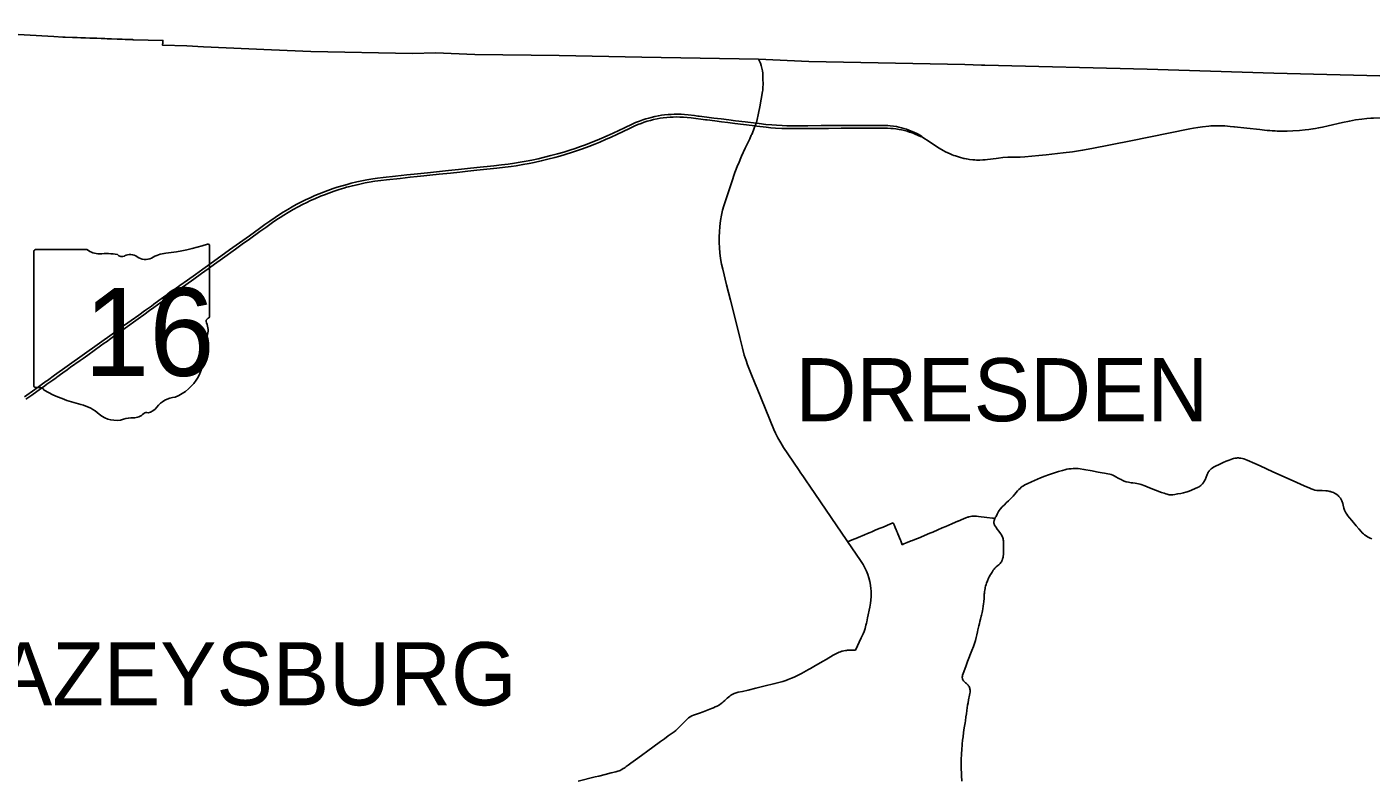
# Model space of a CAD drawing. Extents: x 1761803 to 2441803, y 509895 to 949895.
# Drawn here: x 2077957 to 2120541, y 859538 to 883403 of the extents above; entities that cross this region are included whole.
import ezdxf

# ---------------------------------------------------------------- set-up
doc = ezdxf.new("R2010")
doc.units = 0
for name, color, linetype in [('GM_X_County', 7, 'Continuous'), ('GM_X_County_Road', 7, 'Continuous'), ('GM_X_Minor_Lake', 7, 'Continuous'), ('GM_X_Township_Road', 7, 'Continuous')]:
    doc.layers.add(name, color=color, linetype=linetype)

msp = doc.modelspace()

# ---------------------------------------------------------------- linework, layer by layer
at = {"layer": 'GM_X_County'}
msp.add_lwpolyline([(2073355, 883403), (2078806, 883101), (2079100, 883079), (2079172, 883079), (2079403, 883070), (2079554, 883063), (2079668, 883059), (2079750, 883056), (2079816, 883053), (2079947, 883049), (2080078, 883046), (2080176, 883044), (2080307, 883039), (2080422, 883033), (2080504, 883028), (2080639, 883022), (2080813, 883013), (2080878, 883011), (2080976, 883009), (2081074, 883006), (2081255, 883000), (2081305, 882998), (2081323, 882996), (2081333, 882993), (2081338, 882991), (2082266, 882974), (2082260, 882880), (2082255, 882851), (2082249, 882829), (2083019, 882800), (2083552, 882776), (2085709, 882680), (2086949, 882622), (2090175, 882557), (2090899, 882579), (2092146, 882528), (2094817, 882501), (2097434, 882447), (2101139, 882380), (2102727, 882302), (2107674, 882210), (2108199, 882192), (2108299, 882191), (2113442, 882063), (2117464, 881939), (2121664, 881828)], dxfattribs=at)
at = {"layer": 'GM_X_Minor_Lake'}
for points in [[(2101275, 881509), (2101277, 881555), (2101276, 881785), (2101273, 881844), (2101268, 881937), (2101259, 882015), (2101243, 882096), (2101222, 882175), (2101194, 882253), (2101139, 882380)], [(2101135, 880666), (2101174, 880874), (2101260, 881359), (2101266, 881400), (2101269, 881430), (2101272, 881457), (2101274, 881494), (2101275, 881509)], [(2077877, 871679), (2078210, 871918), (2078570, 872176), (2078608, 872203), (2078836, 872367), (2080660, 873672), (2080913, 873853), (2081260, 874101), (2081500, 874273), (2081687, 874406), (2081900, 874559), (2081977, 874614), (2082141, 874732), (2082286, 874837), (2082566, 875036), (2082806, 875208), (2083047, 875379), (2083300, 875561), (2083526, 875723), (2083753, 875887), (2084379, 876335), (2085005, 876785), (2085325, 877014), (2085498, 877138), (2085658, 877252), (2085820, 877364), (2085956, 877455), (2086081, 877535), (2086221, 877619), (2086363, 877701), (2086492, 877772), (2086637, 877848), (2086784, 877920), (2086933, 877990), (2087082, 878056), (2087218, 878113), (2087355, 878168), (2087494, 878219), (2087664, 878279), (2087788, 878320), (2087992, 878381), (2088028, 878391), (2088134, 878422), (2088229, 878447), (2088405, 878489), (2088565, 878524), (2088726, 878555), (2088919, 878589), (2089065, 878611), (2089244, 878633), (2089635, 878677), (2089994, 878714), (2090222, 878737), (2090434, 878759), (2090647, 878781), (2091315, 878852), (2091625, 878884), (2091918, 878915), (2092212, 878947), (2092750, 879002), (2092995, 879029), (2093207, 879056), (2093401, 879084), (2093580, 879112), (2093773, 879147), (2093950, 879182), (2094159, 879226), (2094351, 879271), (2094557, 879323), (2094763, 879379), (2094968, 879438), (2095156, 879496), (2095328, 879552), (2095499, 879610), (2095653, 879667), (2095836, 879738), (2096019, 879810), (2096171, 879873), (2096336, 879946), (2096529, 880036), (2096884, 880206), (2097136, 880325), (2097241, 880371), (2097363, 880419), (2097471, 880458), (2097564, 880489), (2097658, 880516), (2097738, 880536), (2097849, 880563), (2097961, 880586), (2098058, 880602), (2098156, 880614), (2098270, 880626), (2098368, 880632), (2098466, 880636), (2098564, 880636), (2098679, 880633), (2098793, 880626), (2098907, 880615), (2099102, 880592), (2099216, 880578), (2099256, 880574), (2099493, 880545), (2099720, 880516), (2099948, 880487), (2100192, 880457), (2100404, 880430), (2100713, 880393), (2101057, 880350), (2101153, 880338), (2101364, 880314), (2101560, 880295), (2101708, 880284), (2101888, 880275), (2102036, 880270), (2102200, 880269), (2102462, 880269), (2102692, 880271), (2103118, 880274), (2103265, 880275), (2103364, 880275), (2103708, 880278), (2104053, 880281), (2104299, 880282), (2104950, 880282), (2105031, 880283), (2105146, 880281), (2105227, 880277), (2105309, 880270), (2105406, 880259), (2105503, 880243), (2105583, 880227), (2105663, 880208), (2105741, 880186), (2105819, 880161), (2105896, 880134), (2106002, 880091), (2106077, 880058), (2106131, 880031), (2106197, 879999), (2106263, 879963), (2106285, 879946), (2106310, 879921)], [(2101012, 880221), (2101029, 880266), (2101057, 880350), (2101066, 880377), (2101093, 880472), (2101126, 880616), (2101135, 880666)], [(2077928, 871603), (2078114, 871736), (2078274, 871851), (2078528, 872032), (2078594, 872080), (2078781, 872214), (2078884, 872288), (2078901, 872300), (2079101, 872444), (2079234, 872540), (2079340, 872617), (2079648, 872835), (2079741, 872901), (2079888, 873007), (2080287, 873294), (2080407, 873380), (2080474, 873427), (2080621, 873533), (2080655, 873557), (2081486, 874155), (2081659, 874280), (2081846, 874413), (2081977, 874508), (2082098, 874595), (2082605, 874957), (2082792, 875090), (2082892, 875161), (2082993, 875232), (2083246, 875414), (2083485, 875588), (2083698, 875740), (2083898, 875884), (2084151, 876066), (2084565, 876361), (2084777, 876515), (2085005, 876676), (2085337, 876915), (2085524, 877049), (2085738, 877202), (2085872, 877296), (2085981, 877369), (2086092, 877439), (2086232, 877524), (2086388, 877614), (2086546, 877701), (2086692, 877778), (2086824, 877844), (2086942, 877900), (2087078, 877959), (2087259, 878035), (2087381, 878084), (2087519, 878136), (2087690, 878196), (2087845, 878247), (2088002, 878296), (2088087, 878321), (2088144, 878337), (2088271, 878370), (2088415, 878403), (2088672, 878457), (2088801, 878482), (2088979, 878511), (2089174, 878538), (2089353, 878560), (2089777, 878604), (2090103, 878638), (2090316, 878660), (2090528, 878681), (2090723, 878701), (2091017, 878732), (2091375, 878772), (2091669, 878802), (2091930, 878830), (2092207, 878860), (2092843, 878926), (2093104, 878955), (2093299, 878981), (2093461, 879005), (2093671, 879040), (2093865, 879075), (2094025, 879107), (2094249, 879158), (2094456, 879207), (2094678, 879265), (2094836, 879308), (2095009, 879360), (2095244, 879433), (2095368, 879474), (2095554, 879540), (2095754, 879614), (2095952, 879691), (2096104, 879753), (2096285, 879831), (2096465, 879910), (2096643, 879993), (2097042, 880185), (2097191, 880253), (2097312, 880305), (2097418, 880347), (2097511, 880381), (2097605, 880411), (2097716, 880442), (2097811, 880465), (2097924, 880489), (2098021, 880506), (2098118, 880520), (2098232, 880533), (2098331, 880542), (2098429, 880547), (2098527, 880548), (2098642, 880547), (2098757, 880542), (2098872, 880533), (2099002, 880519), (2099452, 880463), (2099507, 880456), (2099751, 880426), (2099962, 880400), (2100158, 880374), (2100385, 880345), (2100929, 880278)], [(2100333, 878630), (2100389, 878794), (2100482, 879031), (2100497, 879068), (2100599, 879310), (2100713, 879565), (2100855, 879860), (2100906, 879970), (2100918, 879994), (2100976, 880130), (2101012, 880221)], [(2100929, 880278), (2101029, 880266), (2101085, 880259), (2101378, 880224), (2101525, 880209), (2101672, 880198), (2101868, 880187), (2102015, 880182), (2102179, 880180), (2102442, 880182), (2102704, 880185), (2103294, 880186), (2103353, 880187), (2103753, 880189), (2104311, 880193), (2104725, 880192)], [(2110245, 879351), (2110784, 879408), (2111077, 879445), (2111402, 879496), (2111692, 879550), (2112931, 879796), (2113494, 879909), (2114797, 880171), (2114915, 880194), (2115055, 880218), (2115201, 880239), (2115397, 880259), (2115468, 880264), (2115587, 880268), (2115650, 880269), (2115774, 880267), (2115905, 880263), (2116075, 880250)], [(2116075, 880250), (2116191, 880240), (2116215, 880239), (2116606, 880195), (2117014, 880148), (2117159, 880133), (2117244, 880124), (2117332, 880118), (2117409, 880112), (2117445, 880109)], [(2117445, 880109), (2117498, 880105), (2117564, 880102), (2117701, 880099), (2117881, 880101), (2118062, 880107), (2118275, 880120), (2118455, 880138), (2118565, 880153), (2118699, 880172), (2118783, 880187), (2118874, 880204), (2119000, 880230), (2119181, 880270), (2119629, 880372), (2119854, 880420), (2120047, 880455), (2120242, 880481), (2120405, 880497), (2120534, 880506), (2120612, 880511), (2120944, 880526)], [(2104725, 880192), (2104894, 880191), (2105109, 880192), (2105224, 880190), (2105323, 880185), (2105405, 880179), (2105487, 880169), (2105585, 880154), (2105666, 880138), (2105762, 880116), (2105842, 880095), (2105920, 880070), (2105998, 880042), (2106055, 880020), (2106216, 879949), (2106261, 879931), (2106280, 879925), (2106310, 879921)], [(2106310, 879921), (2106569, 879753), (2106774, 879616), (2106857, 879563), (2106984, 879488), (2107056, 879448), (2107130, 879412), (2107205, 879378), (2107266, 879354), (2107327, 879330), (2107372, 879314), (2107435, 879294), (2107500, 879273), (2107638, 879234), (2107657, 879230), (2107722, 879218), (2107774, 879210)], [(2108666, 879237), (2108741, 879247), (2108871, 879261), (2109035, 879270), (2109428, 879278), (2109576, 879286), (2110017, 879327), (2110245, 879351)], [(2107774, 879210), (2107821, 879203), (2107920, 879192), (2107986, 879186), (2108036, 879184), (2108149, 879184), (2108241, 879187), (2108310, 879192), (2108383, 879199), (2108666, 879237)], [(2102529, 869187), (2102456, 869295), (2102419, 869348), (2102059, 869877), (2101923, 870082), (2101838, 870222), (2101750, 870380), (2101676, 870526), (2101623, 870645), (2101090, 871951), (2101032, 872091), (2100891, 872437), (2100787, 872696), (2100738, 872835), (2100684, 873007), (2100623, 873228), (2100540, 873562), (2100370, 874247), (2100247, 874741), (2100122, 875233), (2099999, 875727), (2099964, 875887), (2099933, 876064), (2099909, 876243), (2099895, 876406), (2099888, 876570), (2099888, 876750), (2099894, 876914), (2099899, 876973), (2099904, 877019), (2099909, 877077), (2099934, 877272), (2099962, 877434), (2099998, 877593), (2100037, 877735), (2100118, 877985), (2100331, 878623), (2100333, 878630)], [(2108618, 867824), (2108645, 867870), (2108658, 867895), (2108691, 867966), (2108721, 868024), (2108738, 868053), (2108756, 868081), (2108787, 868119), (2108854, 868192), (2108922, 868263), (2108979, 868322), (2109050, 868390), (2109144, 868481), (2109201, 868539), (2109256, 868600), (2109342, 868699), (2109386, 868748), (2109421, 868782), (2109458, 868815), (2109484, 868836), (2109525, 868864), (2109568, 868889), (2109640, 868924), (2109783, 868989), (2110070, 869118), (2110204, 869171), (2110318, 869210), (2110417, 869243), (2110634, 869313), (2110759, 869352), (2110839, 869373), (2110903, 869387), (2110968, 869398), (2111034, 869406), (2111099, 869411), (2111149, 869412), (2111214, 869411), (2111264, 869407), (2111329, 869400), (2111443, 869381), (2111701, 869333), (2111845, 869306), (2111891, 869298), (2112018, 869276), (2112099, 869262), (2112196, 869246), (2112261, 869233), (2112309, 869220), (2112355, 869202), (2112400, 869181), (2112458, 869151), (2112530, 869110), (2112572, 869085), (2112619, 869059), (2112658, 869038), (2112692, 869023), (2112722, 869010), (2112750, 869000), (2112778, 868992), (2112859, 868975), (2112939, 868961), (2112987, 868955), (2113069, 868947), (2113118, 868940), (2113167, 868930), (2113214, 868918), (2113261, 868902), (2113369, 868862), (2113522, 868802), (2113904, 868656), (2113980, 868627), (2114038, 868606), (2114084, 868593), (2114144, 868580), (2114183, 868577), (2114219, 868577), (2114256, 868580), (2114324, 868590), (2114409, 868605), (2114510, 868623), (2114597, 868643), (2114667, 868660), (2114714, 868674), (2114776, 868696), (2114852, 868726), (2114972, 868778), (2115046, 868812), (2115089, 868835), (2115117, 868853), (2115143, 868872), (2115179, 868905), (2115201, 868928), (2115222, 868953), (2115241, 868979), (2115257, 869007), (2115279, 869051), (2115317, 869142), (2115348, 869218), (2115369, 869263), (2115383, 869292), (2115400, 869321), (2115410, 869334), (2115431, 869360), (2115454, 869384), (2115479, 869405), (2115506, 869425), (2115548, 869450), (2115607, 869481), (2115726, 869537), (2115859, 869599), (2115949, 869640), (2116039, 869679), (2116101, 869701), (2116148, 869716), (2116180, 869725), (2116228, 869736), (2116277, 869743), (2116310, 869745), (2116343, 869746), (2116376, 869744), (2116409, 869740), (2116464, 869730), (2116511, 869715), (2116560, 869696), (2116609, 869675), (2116687, 869641), (2116784, 869597), (2116927, 869535), (2117182, 869422), (2117271, 869381), (2117525, 869267), (2117885, 869106), (2118185, 868973), (2118424, 868865), (2118597, 868786), (2118644, 868765), (2118700, 868744), (2118758, 868729), (2118825, 868717), (2118890, 868713), (2118986, 868710), (2119105, 868704), (2119158, 868699), (2119205, 868692), (2119234, 868687), (2119267, 868678), (2119275, 868675), (2119305, 868665), (2119344, 868646), (2119386, 868626), (2119422, 868605), (2119462, 868579), (2119493, 868553), (2119521, 868524), (2119545, 868495), (2119567, 868467), (2119590, 868430), (2119613, 868391), (2119628, 868355), (2119638, 868331), (2119648, 868300), (2119660, 868252), (2119681, 868156), (2119689, 868125), (2119700, 868094), (2119719, 868050), (2119742, 868007), (2119768, 867965), (2119806, 867912), (2119857, 867848), (2119931, 867761), (2120071, 867600), (2120155, 867499), (2120229, 867413), (2120262, 867377), (2120298, 867343), (2120335, 867312), (2120387, 867273), (2120428, 867246), (2120470, 867221), (2120514, 867200), (2120559, 867181)], [(2103956, 867094), (2103933, 867130), (2103433, 867863), (2102758, 868852), (2102646, 869016), (2102533, 869181), (2102529, 869187)], [(2107446, 867739), (2107464, 867747), (2107629, 867819), (2107704, 867850), (2107750, 867865), (2107774, 867873), (2107797, 867879), (2107845, 867889), (2107893, 867896), (2107942, 867900), (2107991, 867901), (2108040, 867900), (2108105, 867895), (2108363, 867864)], [(2108363, 867864), (2108364, 867864), (2108545, 867843), (2108581, 867836), (2108618, 867824)], [(2103956, 867094), (2103995, 867106), (2104009, 867111), (2104026, 867118), (2104157, 867172), (2104215, 867196), (2104293, 867229), (2104490, 867311), (2104582, 867348), (2104672, 867386), (2104722, 867407), (2104771, 867428), (2104854, 867463), (2104984, 867516), (2105083, 867556), (2105318, 867654), (2105404, 867689)], [(2105404, 867689), (2105433, 867623), (2105464, 867547), (2105495, 867472), (2105508, 867442), (2105520, 867413), (2105539, 867369), (2105551, 867340), (2105631, 867146), (2105642, 867116), (2105653, 867086), (2105666, 867056), (2105689, 866997)], [(2105689, 866997), (2105740, 867021), (2105841, 867063), (2105975, 867118), (2106017, 867135), (2106140, 867183), (2106167, 867194), (2106200, 867208), (2106562, 867360), (2106652, 867399), (2106818, 867469), (2106953, 867527), (2107073, 867579), (2107254, 867656), (2107281, 867668), (2107446, 867739)], [(2107577, 859502), (2107573, 859547), (2107567, 859645), (2107563, 859760), (2107557, 859891), (2107556, 860021), (2107556, 860138), (2107559, 860236), (2107562, 860320), (2107567, 860401), (2107573, 860480), (2107578, 860550), (2107582, 860611), (2107588, 860674), (2107598, 860800), (2107613, 860907), (2107632, 861051), (2107652, 861190), (2107679, 861349), (2107690, 861412), (2107706, 861539), (2107721, 861634), (2107737, 861747), (2107759, 861910), (2107772, 861991), (2107787, 862079), (2107820, 862233), (2107832, 862280), (2107838, 862329), (2107839, 862361), (2107837, 862393), (2107832, 862425), (2107829, 862441), (2107818, 862471), (2107805, 862501), (2107789, 862530), (2107779, 862543), (2107758, 862567), (2107746, 862578), (2107722, 862601), (2107696, 862620), (2107658, 862652), (2107634, 862676), (2107624, 862688), (2107614, 862702), (2107606, 862717), (2107599, 862733), (2107594, 862749), (2107591, 862765), (2107589, 862782), (2107590, 862799), (2107594, 862832), (2107601, 862864), (2107616, 862912), (2107666, 863051), (2107711, 863174), (2107755, 863298), (2107796, 863405), (2107850, 863542), (2107893, 863649), (2107940, 863772), (2107974, 863862), (2108004, 863957), (2108032, 864058), (2108051, 864139), (2108070, 864235), (2108085, 864302), (2108095, 864342), (2108107, 864387), (2108116, 864424), (2108133, 864499), (2108147, 864562), (2108168, 864639), (2108191, 864732), (2108199, 864764), (2108218, 864848), (2108228, 864903), (2108238, 864966), (2108251, 865045), (2108263, 865127), (2108271, 865192), (2108280, 865304), (2108283, 865384), (2108287, 865433), (2108291, 865463), (2108293, 865478), (2108297, 865510), (2108304, 865558), (2108312, 865606), (2108318, 865638), (2108329, 865686), (2108342, 865734), (2108358, 865781), (2108388, 865857), (2108421, 865933), (2108442, 865977), (2108462, 866012), (2108466, 866020), (2108491, 866063), (2108535, 866132), (2108571, 866186), (2108600, 866226), (2108622, 866251), (2108644, 866275), (2108668, 866297), (2108718, 866339), (2108743, 866360), (2108767, 866383), (2108789, 866406), (2108809, 866431), (2108827, 866458), (2108843, 866486), (2108849, 866501), (2108856, 866516), (2108861, 866530), (2108866, 866545), (2108875, 866572), (2108882, 866602), (2108886, 866634), (2108891, 866683), (2108893, 866765), (2108894, 866863), (2108895, 866962), (2108893, 867059), (2108890, 867124), (2108886, 867156), (2108880, 867188), (2108872, 867219), (2108860, 867250), (2108846, 867279), (2108831, 867307), (2108804, 867348), (2108747, 867428), (2108698, 867493), (2108649, 867560), (2108630, 867587), (2108613, 867615), (2108606, 867630), (2108599, 867646), (2108595, 867662), (2108591, 867678), (2108590, 867695), (2108590, 867712), (2108592, 867729), (2108595, 867746), (2108600, 867762), (2108618, 867824)], [(2104697, 865595), (2104681, 865719), (2104658, 865833), (2104629, 865944), (2104593, 866054), (2104551, 866161), (2104501, 866265), (2104446, 866366), (2104367, 866492), (2103956, 867094)], [(2104209, 863651), (2104389, 864045), (2104447, 864175), (2104479, 864251), (2104511, 864344), (2104538, 864447), (2104553, 864506), (2104564, 864554), (2104592, 864680), (2104664, 865017), (2104685, 865147), (2104696, 865244), (2104703, 865359), (2104704, 865396), (2104704, 865429), (2104704, 865471), (2104703, 865502), (2104701, 865535), (2104697, 865594), (2104697, 865595)], [(2103156, 863295), (2103279, 863365), (2103499, 863496), (2103600, 863550), (2103690, 863591), (2103729, 863606), (2103774, 863621), (2103793, 863628), (2103839, 863639), (2103894, 863645), (2103932, 863649), (2103942, 863651), (2103990, 863654), (2104075, 863654), (2104209, 863651)], [(2102183, 862765), (2102212, 862777), (2102285, 862810), (2102331, 862831), (2102477, 862906), (2102500, 862918), (2102649, 863002), (2102721, 863041), (2102777, 863076), (2102890, 863142), (2103156, 863295)], [(2095419, 859507), (2095956, 859639), (2096072, 859668), (2096279, 859719), (2096470, 859766), (2096614, 859801), (2096681, 859822), (2096718, 859835), (2096750, 859848), (2096780, 859863), (2096809, 859880), (2096846, 859902), (2096879, 859922), (2096908, 859940), (2096946, 859968), (2097002, 860009), (2097092, 860073), (2097242, 860183), (2097426, 860318), (2097626, 860463), (2097784, 860580), (2098034, 860764), (2098153, 860851), (2098272, 860939), (2098337, 860988), (2098457, 861072), (2098510, 861112), (2098560, 861154), (2098644, 861233), (2098779, 861375), (2098859, 861457), (2098889, 861485), (2098921, 861509), (2098974, 861546), (2099017, 861570), (2099077, 861596), (2099169, 861630), (2099261, 861663), (2099385, 861707), (2099646, 861806), (2099707, 861830), (2099765, 861856), (2099826, 861886), (2099898, 861926), (2099952, 861963), (2099984, 861989), (2100019, 862017), (2100063, 862058), (2100146, 862139), (2100221, 862203), (2100260, 862231), (2100317, 862263), (2100362, 862282), (2100424, 862304), (2100487, 862321), (2100631, 862349), (2100808, 862386), (2101046, 862448), (2101300, 862511), (2101653, 862599), (2101903, 862667), (2101997, 862695), (2102075, 862722), (2102183, 862765)]]:
    msp.add_lwpolyline(points, dxfattribs=at)
at = {"layer": 'GM_X_Township_Road'}
for p, q in [((2083745, 874241), (2083745, 876452)), ((2078176, 876274), (2078176, 872048)), ((2079862, 876347), (2078231, 876347)), ((2083744, 874241), (2083745, 874241))]:
    msp.add_line(p, q, dxfattribs=at)
for centre, radius, start, end in [((2081761, 882109), 5905, 275.8445, 288.9065), ((2083683, 876461), 62, 351.8621, 97.738), ((2078240, 876283), 64.5, 98.1301, 188.1301), ((2080250, 876837), 626, 231.6195, 271.1119), ((2080457, 873974), 2246, 80.4867, 94.9883), ((2080967, 876305), 181, 219.7921, 297.1024), ((2081232, 875817), 375, 54.4667, 119.1411), ((2081717, 876487), 452, 233.8562, 294.8282), ((2082514, 875056), 1188, 97.3462, 120.7689), ((2083678, 874232), 66.3, 289.6038, 7.7341), ((2083730, 874078), 95.9, 107.944, 210.337), ((2083120, 873799), 576, 340.033, 23.6496), ((2083967, 873315), 419, 136.8065, 186.9296), ((2082092, 873034), 1477, 292.3089, 8.9858), ((2078240, 872038), 65.1, 171.9584, 258.3066), ((2078250, 872471), 497, 267.339, 280.6039), ((2078352, 871804), 179, 29.7484, 93.2717), ((2080613, 875601), 4265, 240.4129, 257.1985), ((2079342, 870149), 1334, 47.1842, 75.836), ((2081690, 871638), 477, 282.8732, 323.2771), ((2082715, 870861), 809, 94.4031, 142.5768), ((2080785, 871783), 847, 230.7004, 286.2918), ((2081274, 870321), 696, 85.6951, 111.2099), ((2081336, 871466), 451, 268.777, 315.5493), ((2081744, 871057), 127, 65.7517, 132.6484)]:
    msp.add_arc(centre, radius, start, end, dxfattribs=at)

# ---------------------------------------------------------------- texts
at = {"layer": 'GM_X_County_Road'}
for s, p in [('DRESDEN', (2102305, 870908)), ('FRAZEYSBURG', (2073413, 861908))]:
    msp.add_text(s, height=2000, rotation=0, dxfattribs=at).set_placement(p)
at = {"layer": 'GM_X_Township_Road'}
msp.add_text('16', height=2784.4, dxfattribs=at).set_placement((2079764, 872346))

doc.saveas('drawing.dxf')
